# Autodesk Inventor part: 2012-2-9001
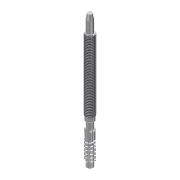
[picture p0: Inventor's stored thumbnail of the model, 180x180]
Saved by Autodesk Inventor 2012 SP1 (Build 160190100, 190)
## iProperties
Created: 2007-11
Part Number: 2012-2-9001
Material: Stainless Steel
Document SubType Name: Modeling
Designer: JJ
Density: 8.08 g/cm^3
Mass: 101.36 g
Surface Area: 47.5454 cm^2
Volume: 12.5446 cm^3
Description: BALL SCREW SHAFT
CustomPartVersion: 1
Component Category: Lower Component
Author: JJ
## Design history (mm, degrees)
sketch "Sketch5"
  geometry: L1 (0, -13)-(0, 108); L2 (0, -13)-(-4, -13); L3 (-4, -13)-(-4, 17); L4 (-4, 17)-(-3, 17); L5 (-3, 17)-(-3, 23); L6 (-3, 23)-(-4, 23); L7 (-4, 23)-(-4, 93); L8 (-4, 93)-(-3, 93); L9 (-3, 93)-(-3, 108); L10 (-3, 108)-(0, 108); 2 further points
  constraints: 20 end point, 6 parallel, 2 collinear, 1 coincident, 1 perpendicular, 1 point on line, 1 vertical
  dimensions: "ShaftOD" = 8 diameter of L3 L1; "d31" = 30 distance of L2.end L3.end; "d32" = 6 distance between parallel lines of L6 L4; "d33" = 70 distance of L6.end L7.end; "d34" = 15 distance between parallel lines of L10 L8; "d42" = 6 diameter of L5 L1; "d66" = 13 distance from line of point (0, 0) L2
revolve "Revolution3" sketch "Sketch5" stored, may be unused: angle "d37" = 90 deg
chamfer "Chamfer4" distance "d18" = 4.66; stored, may be unused: second distance "d19" = 0.93, angle "d20" = 45 deg
chamfer "Chamfer3" distance "d14" = 1; stored, may be unused: second distance "d15" = 0.125, angle "d16" = 30 deg
chamfer "Chamfer1" distance "d8" = 1; stored, may be unused: second distance "d9" = 0.125, angle "d10" = 45 deg
thread "Thread1" dims "d26" = 10, "d27" = 0
sketch "Sketch11"
  geometry: L1 (-4, -13)-(-3, -13); L2 (-3, -13)-(-3, -14); L3 (-3, -14)-(-4, -14); L4 (-4, -14)-(-4, -13); L5 (-4, -13)-(-4, 16) reference; L6 (-3, -13)-(-4, -13); L7 (-4, -13)-(-4, -8); L8 (-4, -8)-(-3, -8); L9 (-3, -8)-(-3, -13); L10 (0, -22.249)-(0, 20.041) reference; L11 (4, -13)-(-4, -13) reference; L12 (-1, -13)-(0, -13); L13 (0, -13)-(0, -14); A1 r 1 centre (0, -13) between (-1, -13) and (0, -14)
  constraints: 20 end point, 4 parallel, 3 perpendicular, 2 horizontal, 2 point on circle, 2 point on line, 1 centre point, 1 collinear, 1 midpoint
  dimensions: "d80" = 1 distance of L1.end L2.end (= d81); "d81" = 1 distance of L2.end L3.end; "d82" = 5 distance of L8.end L1.end; "d83" = 1 radius of A1
revolve "Revolution4" stored, may be unused: angle "d92" = 90 deg
revolve "Revolution5" stored, may be unused: angle "d93" = 90 deg
node "Involute Splining1"
coil "Coil2" pitch "d84" = 3; turns "d86" = 7.5; dims "d85" = 10, "d87" = 0, angle "d88" = 90 deg, angle "d89" = 90 deg, "d90" = 0, "d91" = 0
body "Solid1"
feature "Shaft Groove"
